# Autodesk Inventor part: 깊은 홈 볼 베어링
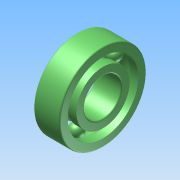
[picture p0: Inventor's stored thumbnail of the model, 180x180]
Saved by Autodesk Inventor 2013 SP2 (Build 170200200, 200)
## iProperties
Created: 2026-07
Part Number: 깊은 홈 볼 베어링
Material: Generic
Document SubType Name: Modeling
Designer: 601
Density: 1 g/cm^3
Author: 601
변환 표준: STEP AP214IS
전처리기: Build: 200, Release: 2013 SP2 Update 6 - Date: Thu 07/17/2014
전송 단위: 밀리미터
불확실성: 0.01
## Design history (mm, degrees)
node "깊은 홈 볼 베어링 62031"
body "Solid1"
node "Solid1_1"
node "Solid1_2"
node "Solid1_3"
node "Solid1_4"
node "Solid1_5"
node "Solid1_6"
node "Solid1_7"
node "Solid1_8"
node "기준1"
node "기준2"
node "기준3"
node "기준4"
node "기준5"
node "기준6"
node "기준7"
node "기준8"
node "기준9"
